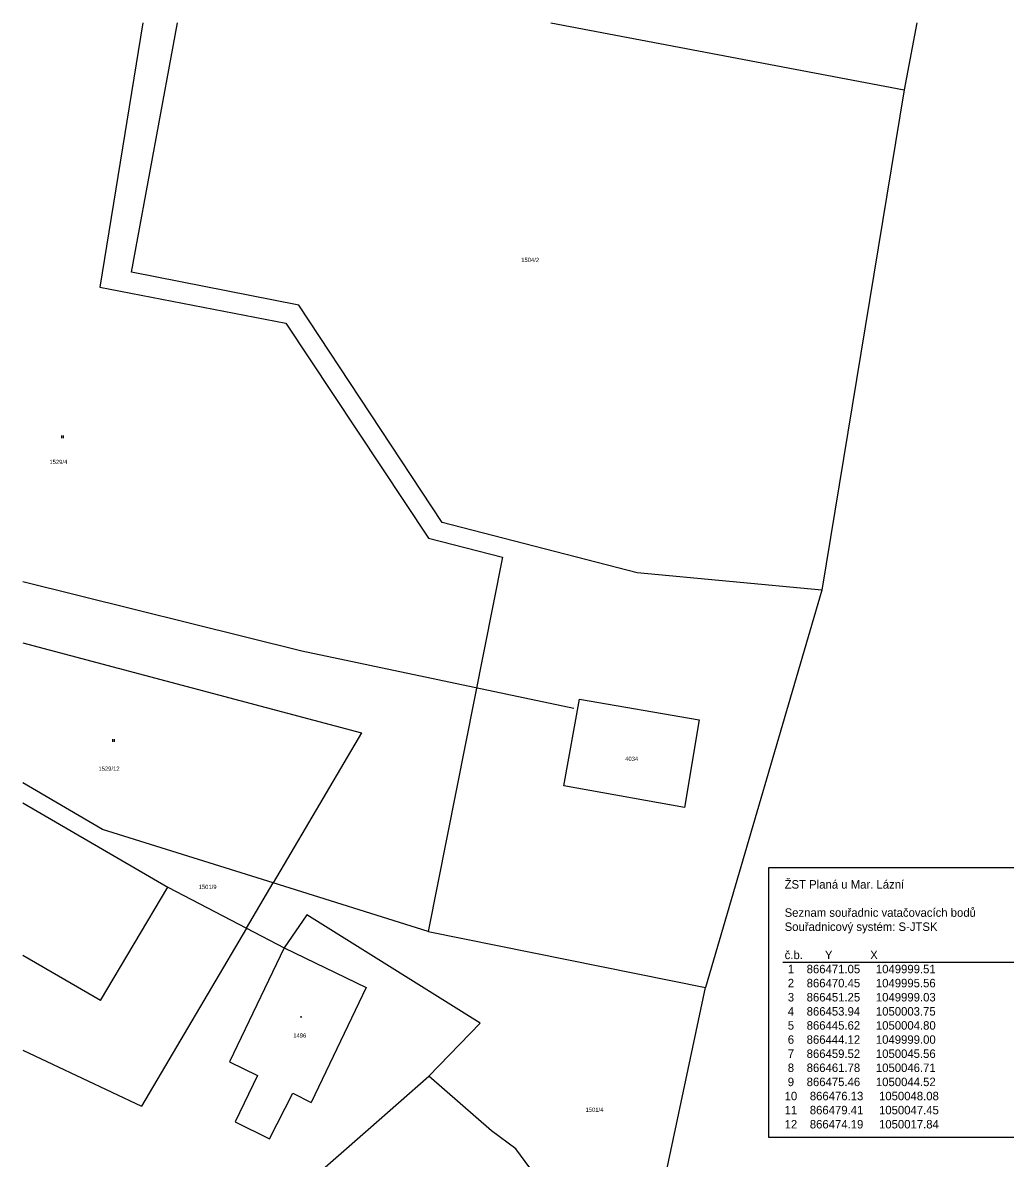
# Model space of a CAD drawing. Extents: x -866624 to -866276, y -1050208 to -1049940.
# Drawn here: x -866623.7 to -866507.6, y -1050074.4 to -1049940.2 of the extents above; entities that cross this region are included whole.
import ezdxf

# ---------------------------------------------------------------- set-up
doc = ezdxf.new("R2010")
doc.units = 0
for name, color, linetype in [('00_BODY VYTYČ', 7, 'Continuous'), ('Default', 7, 'Continuous'), ('Hranice', 7, 'Continuous'), ('Hranice další', 7, 'Continuous'), ('Hranice-budov', 7, 'Continuous'), ('Parcela-pozemkova', 7, 'Continuous'), ('Parcela-stavebni', 7, 'Continuous'), ('znacky-budov', 7, 'Continuous'), ('Znacky-kultury', 7, 'Continuous')]:
    doc.layers.add(name, color=color, linetype=linetype)

# ---------------------------------------------------------------- blocks, each defined once
blk = doc.blocks.new('p_louka')
at = {"layer": 'Default'}
for p, q in [((-0.47, 0.72), (-0.47, -0.78)), ((0.53, 0.72), (0.53, -0.78))]:
    blk.add_line(p, q, dxfattribs=at)
blk = doc.blocks.new('s_zdena')
at = {"layer": 'Default'}
blk.add_circle((0, 0), 0.175, dxfattribs=at)
for start, end in [(0, 180), (180, 0)]:
    blk.add_arc((0, 0), 0.0875, start, end, dxfattribs=at)

msp = doc.modelspace()

# ---------------------------------------------------------------- linework, layer by layer
at = {"layer": '00_BODY VYTYČ'}
msp.add_line((-866533.91, -1050051.21), (-866505.16, -1050051.21), dxfattribs=at)
msp.add_lwpolyline([(-866535.57, -1050040.03), (-866503.34, -1050040.03), (-866503.34, -1050071.89), (-866535.57, -1050071.89)], close=True, dxfattribs=at)
at = {"layer": 'Hranice'}
for p, q in [((-866609.52, -1049940.23), (-866614.62, -1049971.47)), ((-866610.86, -1049969.71), (-866605.42, -1049940.23)), ((-866561.33, -1049940.23), (-866519.58, -1049948.15)), ((-866518.1, -1049940.23), (-866519.58, -1049948.15)), ((-866519.58, -1049948.15), (-866529.3, -1050007.24)), ((-866591.11, -1049973.59), (-866610.86, -1049969.71)), ((-866614.62, -1049971.47), (-866592.64, -1049975.73)), ((-866574.16, -1049999.25), (-866591.11, -1049973.59)), ((-866592.64, -1049975.73), (-866575.79, -1050001.13)), ((-866551.13, -1050005.19), (-866574.16, -1049999.25)), ((-866575.79, -1050001.13), (-866567.03, -1050003.34)), ((-866567.03, -1050003.34), (-866575.81, -1050047.56)), ((-866529.3, -1050007.24), (-866551.13, -1050005.19)), ((-866529.3, -1050007.24), (-866543.07, -1050054.21)), ((-866623.73, -1050013.47), (-866583.71, -1050024.09)), ((-866559.79, -1050030.38), (-866557.95, -1050020.12)), ((-866557.95, -1050020.12), (-866543.79, -1050022.57)), ((-866543.79, -1050022.57), (-866545.56, -1050032.93)), ((-866583.71, -1050024.09), (-866594.14, -1050041.82)), ((-866614.28, -1050035.51), (-866623.73, -1050030.03)), ((-866545.56, -1050032.93), (-866559.79, -1050030.38)), ((-866623.73, -1050032.38), (-866606.58, -1050042.35)), ((-866594.14, -1050041.82), (-866614.28, -1050035.51)), ((-866597.3, -1050047.19), (-866594.14, -1050041.82)), ((-866575.81, -1050047.56), (-866594.14, -1050041.82)), ((-866606.58, -1050042.35), (-866597.3, -1050047.19)), ((-866590.15, -1050045.59), (-866592.83, -1050049.52)), ((-866569.67, -1050058.39), (-866590.15, -1050045.59)), ((-866597.3, -1050047.19), (-866609.68, -1050068.21)), ((-866597.3, -1050047.19), (-866592.83, -1050049.52)), ((-866575.81, -1050047.56), (-866543.07, -1050054.21)), ((-866592.83, -1050049.52), (-866599.31, -1050062.98)), ((-866592.83, -1050049.52), (-866583.14, -1050054.19)), ((-866583.14, -1050054.19), (-866589.65, -1050067.77)), ((-866565.77, -1050161.24), (-866543.07, -1050054.21)), ((-866575.73, -1050064.67), (-866569.67, -1050058.39)), ((-866623.73, -1050061.6), (-866609.68, -1050068.21)), ((-866599.31, -1050062.98), (-866595.97, -1050064.59)), ((-866595.97, -1050064.59), (-866598.61, -1050070.06)), ((-866582.91, -1050070.98), (-866575.73, -1050064.67)), ((-866568.34, -1050071.11), (-866575.73, -1050064.67)), ((-866594.58, -1050072.05), (-866591.81, -1050066.66)), ((-866591.81, -1050066.66), (-866589.65, -1050067.77)), ((-866598.61, -1050070.06), (-866594.58, -1050072.05)), ((-866618.46, -1050101.87), (-866582.91, -1050070.98)), ((-866565.46, -1050073.25), (-866568.34, -1050071.11)), ((-866563.83, -1050075.48), (-866565.46, -1050073.25))]:
    msp.add_line(p, q, dxfattribs=at)
at = {"layer": 'Hranice další'}
for p, q in [((-866590.75, -1050014.46), (-866623.73, -1050006.26)), ((-866558.6, -1050021.24), (-866590.75, -1050014.46)), ((-866614.54, -1050055.74), (-866606.58, -1050042.35)), ((-866614.54, -1050055.74), (-866623.73, -1050050.4))]:
    msp.add_line(p, q, dxfattribs=at)
at = {"layer": 'Hranice-budov'}
for p, q in [((-866623.73, -1050032.38), (-866606.58, -1050042.35)), ((-866614.54, -1050055.74), (-866606.58, -1050042.35)), ((-866592.83, -1050049.52), (-866599.31, -1050062.98)), ((-866592.83, -1050049.52), (-866583.14, -1050054.19)), ((-866614.54, -1050055.74), (-866623.73, -1050050.4)), ((-866583.14, -1050054.19), (-866589.65, -1050067.77)), ((-866599.31, -1050062.98), (-866595.97, -1050064.59)), ((-866595.97, -1050064.59), (-866598.61, -1050070.06)), ((-866594.58, -1050072.05), (-866591.81, -1050066.66)), ((-866591.81, -1050066.66), (-866589.65, -1050067.77)), ((-866598.61, -1050070.06), (-866594.58, -1050072.05))]:
    msp.add_line(p, q, dxfattribs=at)

# ---------------------------------------------------------------- block references
at = {"layer": 'znacky-budov', "xscale": 0.2, "yscale": 0.20000000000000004}
msp.add_blockref('s_zdena', (-866590.84, -1050057.67), dxfattribs=at)
at = {"layer": 'Znacky-kultury', "xscale": 0.2, "yscale": 0.20000000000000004}
for p in [(-866619.06, -1049989.14), (-866613.03, -1050025.02)]:
    msp.add_blockref('p_louka', p, dxfattribs=at)

# ---------------------------------------------------------------- texts
at = {"layer": '00_BODY VYTYČ'}
for s, p in [('ŽST Planá u Mar. Lázní', (-866533.71, -1050042.51)), ('Seznam souřadnic vatačovacích bodů', (-866533.71, -1050045.84)), ('Souřadnicový systém: S-JTSK', (-866533.71, -1050047.51)), ('č.b.       Y            X', (-866533.71, -1050050.84)), (' 1    866471.05     1049999.51', (-866533.71, -1050052.51)), (' 2    866470.45     1049995.56', (-866533.71, -1050054.17)), (' 3    866451.25     1049999.03', (-866533.71, -1050055.84)), (' 4    866453.94     1050003.75', (-866533.71, -1050057.51)), (' 5    866445.62     1050004.80', (-866533.71, -1050059.17)), (' 6    866444.12     1049999.00', (-866533.71, -1050060.84)), (' 7    866459.52     1050045.56', (-866533.71, -1050062.51)), (' 8    866461.78     1050046.71', (-866533.71, -1050064.17)), (' 9    866475.46     1050044.52', (-866533.71, -1050065.84)), ('10    866476.13     1050048.08', (-866533.71, -1050067.51)), ('11    866479.41     1050047.45', (-866533.71, -1050069.17)), ('12    866474.19     1050017.84', (-866533.71, -1050070.84))]:
    msp.add_text(s, height=1, dxfattribs=at).set_placement(p)
at = {"layer": 'Parcela-pozemkova'}
for s, p in [('1504/2', (-866564.83, -1049968.49)), ('1529/4', (-866620.57, -1049992.36)), ('4034', (-866552.55, -1050027.43)), ('1529/12', (-866614.78, -1050028.59)), ('1501/9', (-866602.94, -1050042.56)), ('1501/4', (-866557.23, -1050068.88))]:
    msp.add_text(s, height=0.5, dxfattribs=at).set_placement(p)
at = {"layer": 'Parcela-stavebni'}
msp.add_text('1496', height=0.5, dxfattribs=at).set_placement((-866591.76, -1050060.12))

doc.saveas('drawing.dxf')
